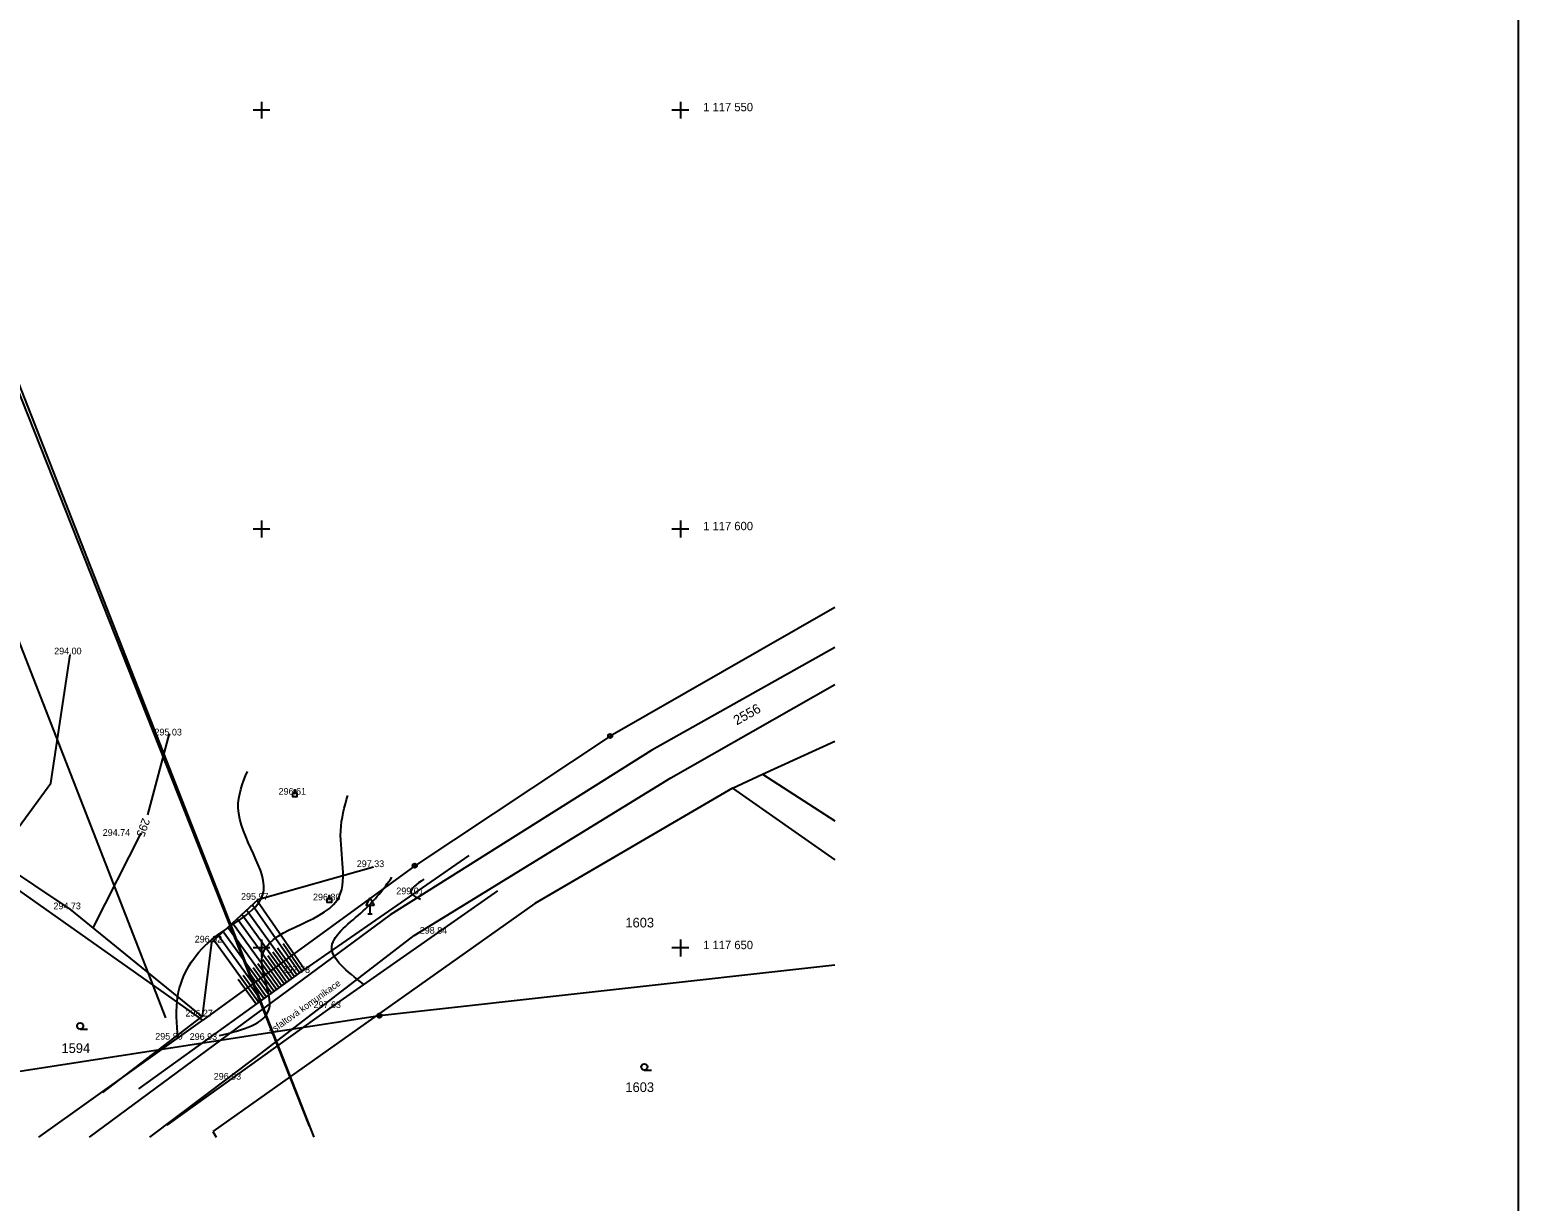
# Model space of a CAD drawing. Extents: x -504375 to -503125, y -1118000 to -1116474.
# Drawn here: x -503927.6 to -503750, y -1117680.2 to -1117540.4 of the extents above; entities that cross this region are included whole.
import ezdxf

# ---------------------------------------------------------------- set-up
doc = ezdxf.new("R2010")
doc.units = 0
for name, color, linetype in [('Druhy povrchů', 7, 'Continuous'), ('Elektro', 7, 'Continuous'), ('Komunikace', 7, 'Continuous'), ('Ploty', 7, 'Continuous'), ('Plynovod', 7, 'Continuous'), ('Podkladové mapy', 7, 'Continuous'), ('Síť dekadická', 7, 'Continuous'), ('Vrstva 34', 7, 'Continuous'), ('Vrstva 48', 7, 'Continuous'), ('Výškopis', 7, 'Continuous'), ('Výšky bodů plotr', 7, 'Continuous'), ('Značky ČSN', 7, 'Continuous')]:
    doc.layers.add(name, color=color, linetype=linetype)

msp = doc.modelspace()

# ---------------------------------------------------------------- linework, layer by layer
at = {"layer": 'Elektro'}
for points in [[(-503956.484, -1117542.839), (-503911.458, -1117658.334)], [(-503936.11, -1117565.73), (-503894.299, -1117671.279)]]:
    msp.add_lwpolyline(points, dxfattribs=at)
at = {"layer": 'Komunikace'}
for points in [[(-503875.235, -1117638.978), (-503895.47, -1117652.98), (-503914.65, -1117666.799)], [(-503911.247, -1117671.145), (-503891.78, -1117657.17), (-503871.792, -1117643.188)]]:
    msp.add_lwpolyline(points, dxfattribs=at)
at = {"layer": 'Ploty'}
msp.add_lwpolyline([(-503918.907, -1117667.255), (-503907.07, -1117658.18), (-503922.82, -1117645.38), (-503931.54, -1117639.57), (-503936.08, -1117638.16), (-503933.06, -1117633.02), (-504033.06, -1117569.97), (-504030.05, -1117581.29)], dxfattribs=at)
at = {"layer": 'Plynovod'}
for points in [[(-503896.264, -1117631.476), (-503895.76, -1117631.476), (-503895.76, -1117631.98), (-503896.264, -1117631.98)], [(-503892.154, -1117644.086), (-503891.65, -1117644.086), (-503891.65, -1117644.59), (-503892.154, -1117644.59)]]:
    msp.add_lwpolyline(points, close=True, dxfattribs=at)
for points in [[(-503895.949, -1117631.476), (-503895.949, -1117631.161), (-503896.075, -1117631.161), (-503896.075, -1117631.476)], [(-503891.839, -1117644.086), (-503891.839, -1117643.771), (-503891.965, -1117643.771), (-503891.965, -1117644.086)]]:
    msp.add_lwpolyline(points, dxfattribs=at)
at = {"layer": 'Podkladové mapy'}
for p, q in [((-503935.19, -1117566.81), (-503893.75, -1117672.579)), ((-503831.557, -1117609.37), (-503858.38, -1117624.71)), ((-503831.557, -1117614.147), (-503853.42, -1117626.38)), ((-503851.15, -1117629.69), (-503831.557, -1117618.557)), ((-503858.38, -1117624.71), (-503881.7, -1117640.18)), ((-503840.19, -1117629.27), (-503831.557, -1117625.306)), ((-503853.42, -1117626.38), (-503884.65, -1117646.03)), ((-503881.76, -1117648.52), (-503851.15, -1117629.69)), ((-503843.77, -1117630.91), (-503840.19, -1117629.27)), ((-503840.19, -1117629.27), (-503831.557, -1117634.845)), ((-503843.77, -1117630.91), (-503867.36, -1117644.69)), ((-503843.77, -1117630.91), (-503831.557, -1117639.488)), ((-503907.01, -1117658.6), (-503933.4, -1117639.97)), ((-503881.7, -1117640.18), (-503907.01, -1117658.6)), ((-503867.36, -1117644.69), (-503905.79, -1117671.91)), ((-503884.65, -1117646.03), (-503920.562, -1117672.584)), ((-503900.58, -1117663), (-503881.76, -1117648.52)), ((-503885.92, -1117658.08), (-503831.557, -1117652.028)), ((-503980.228, -1117672.595), (-503885.92, -1117658.08)), ((-503926.572, -1117672.585), (-503907.01, -1117658.6)), ((-503886.17, -1117658.03), (-503886.12, -1117657.93)), ((-503886.17, -1117658.13), (-503886.17, -1117658.03)), ((-503886.12, -1117658.23), (-503886.17, -1117658.13)), ((-503886.12, -1117657.93), (-503886.07, -1117657.88)), ((-503886.07, -1117658.28), (-503886.12, -1117658.23)), ((-503886.07, -1117657.88), (-503885.97, -1117657.83)), ((-503886.07, -1117657.98), (-503886.07, -1117658.18)), ((-503886.07, -1117658.18), (-503885.97, -1117658.23)), ((-503885.97, -1117658.33), (-503886.07, -1117658.28)), ((-503885.97, -1117657.83), (-503885.87, -1117657.83)), ((-503885.97, -1117658.23), (-503885.97, -1117657.93)), ((-503885.97, -1117657.93), (-503885.87, -1117657.93)), ((-503885.87, -1117658.33), (-503885.97, -1117658.33)), ((-503885.87, -1117657.83), (-503885.77, -1117657.88)), ((-503885.87, -1117657.93), (-503885.87, -1117658.23)), ((-503885.87, -1117658.23), (-503885.77, -1117658.18)), ((-503885.77, -1117658.28), (-503885.87, -1117658.33)), ((-503885.77, -1117657.88), (-503885.72, -1117657.93)), ((-503885.77, -1117658.18), (-503885.77, -1117657.98)), ((-503885.72, -1117658.23), (-503885.77, -1117658.28)), ((-503885.72, -1117657.93), (-503885.67, -1117658.03)), ((-503885.67, -1117658.13), (-503885.72, -1117658.23)), ((-503885.67, -1117658.03), (-503885.67, -1117658.13)), ((-503921.63, -1117659.69), (-503920.755, -1117659.69)), ((-503913.329, -1117672.583), (-503900.58, -1117663)), ((-503854.31, -1117664.58), (-503853.435, -1117664.58)), ((-503905.79, -1117671.91), (-503905.412, -1117672.582))]:
    msp.add_line(p, q, dxfattribs=at)
for centre, radius in [((-503858.38, -1117624.71), 0.25), ((-503858.38, -1117624.71), 0.005), ((-503881.7, -1117640.18), 0.25), ((-503881.7, -1117640.18), 0.005), ((-503921.63, -1117659.315), 0.375), ((-503854.31, -1117664.205), 0.375)]:
    msp.add_circle(centre, radius, dxfattribs=at)
at = {"layer": 'Síť dekadická'}
msp.add_lwpolyline([(-503750, -1117500), (-503750, -1118000), (-504375, -1118000), (-504375, -1117500)], close=True, dxfattribs=at)
at = {"layer": 'Vrstva 34'}
for p, q in [((-503899, -1117550), (-503901, -1117550)), ((-503900, -1117549), (-503900, -1117551)), ((-503849, -1117550), (-503851, -1117550)), ((-503850, -1117549), (-503850, -1117551)), ((-503899, -1117600), (-503901, -1117600)), ((-503900, -1117599), (-503900, -1117601)), ((-503849, -1117600), (-503851, -1117600)), ((-503850, -1117599), (-503850, -1117601)), ((-503899, -1117650), (-503901, -1117650)), ((-503900, -1117649), (-503900, -1117651)), ((-503849, -1117650), (-503851, -1117650)), ((-503850, -1117649), (-503850, -1117651))]:
    msp.add_line(p, q, dxfattribs=at)
at = {"layer": 'Vrstva 48'}
for p, q in [((-503913.569, -1117634.114), (-503910.98, -1117624.419)), ((-503920.051, -1117647.532), (-503914.365, -1117636.297))]:
    msp.add_line(p, q, dxfattribs=at)
msp.add_lwpolyline([(-503931.66, -1117639.187), (-503925.125, -1117630.342), (-503922.834, -1117614.998)], dxfattribs=at)
for points in [[(-503909.973, -1117660.783), (-503909.973, -1117655.708), (-503905.948, -1117649.023), (-503899.829, -1117643.626), (-503902.768, -1117633.276), (-503901.666, -1117628.921)], [(-503904.982, -1117660.461), (-503899.065, -1117657.246), (-503899.91, -1117651.037), (-503890.974, -1117644.311), (-503890.531, -1117636.015), (-503889.685, -1117631.786)], [(-503887.817, -1117654.32), (-503891.589, -1117649.81), (-503887.848, -1117645.577), (-503884.414, -1117641.558)], [(-503880.621, -1117641.805), (-503882.141, -1117643.441), (-503880.994, -1117644.187)]]:
    msp.add_spline(points, degree=3, dxfattribs=at)
at = {"layer": 'Výškopis'}
for p, q in [((-503895.468, -1117652.979), (-503901.088, -1117644.857)), ((-503894.852, -1117652.552), (-503900.531, -1117644.344)), ((-503897.294, -1117654.294), (-503902.894, -1117646.522)), ((-503896.685, -1117653.856), (-503902.338, -1117646.01)), ((-503896.077, -1117653.417), (-503901.783, -1117645.498)), ((-503899.119, -1117655.609), (-503904.559, -1117648.058)), ((-503898.511, -1117655.171), (-503904.004, -1117647.546)), ((-503897.902, -1117654.732), (-503903.449, -1117647.034)), ((-503900.336, -1117656.486), (-503905.67, -1117649.083)), ((-503899.728, -1117656.048), (-503905.115, -1117648.571)), ((-503895.773, -1117653.198), (-503898.066, -1117650.015)), ((-503895.16, -1117652.765), (-503897.42, -1117649.499)), ((-503898.207, -1117654.952), (-503900.415, -1117651.887)), ((-503897.598, -1117654.513), (-503899.827, -1117651.419)), ((-503896.99, -1117654.075), (-503899.24, -1117650.951)), ((-503896.381, -1117653.636), (-503898.653, -1117650.483)), ((-503900.032, -1117656.267), (-503902.176, -1117653.291)), ((-503899.424, -1117655.829), (-503901.589, -1117652.823)), ((-503898.815, -1117655.39), (-503901.002, -1117652.355)), ((-503900.641, -1117656.705), (-503902.764, -1117653.759))]:
    msp.add_line(p, q, dxfattribs=at)
for points in [[(-503886.62, -1117640.35), (-503900.43, -1117644.25)], [(-503900.43, -1117644.25), (-503905.96, -1117649.35)], [(-503905.96, -1117649.35), (-503907.07, -1117658.18)]]:
    msp.add_lwpolyline(points, dxfattribs=at)
at = {"layer": 'Značky ČSN'}
for p, q in [((-503887.05, -1117644.03), (-503887.55, -1117644.93)), ((-503887.05, -1117644.03), (-503886.55, -1117644.93)), ((-503886.55, -1117644.93), (-503887.55, -1117644.93)), ((-503887.3, -1117645.93), (-503886.8, -1117645.93)), ((-503887.05, -1117644.93), (-503887.05, -1117645.93))]:
    msp.add_line(p, q, dxfattribs=at)

# ---------------------------------------------------------------- texts
at = {"layer": 'Druhy povrchů'}
msp.add_text('asfaltová komunikace', height=0.8, rotation=35.67397, dxfattribs=at).set_placement((-503898.813, -1117660.373))
at = {"layer": 'Podkladové mapy'}
msp.add_text('2556', height=1.15, rotation=29.07081, dxfattribs=at).set_placement((-503843.27, -1117623.446))
for s, p in [('1603', (-503856.56, -1117647.549)), ('1594', (-503923.86, -1117662.53)), ('1603', (-503856.56, -1117667.19))]:
    msp.add_text(s, height=1.15, dxfattribs=at).set_placement(p)
at = {"layer": 'Vrstva 34'}
for s, p in [('1 117 550', (-503847.277, -1117550.143)), ('1 117 600', (-503847.277, -1117600.143)), ('1 117 650', (-503847.277, -1117650.143))]:
    msp.add_text(s, height=1, dxfattribs=at).set_placement(p)
at = {"layer": 'Vrstva 48'}
msp.add_text('295', height=1, rotation=249.99011, dxfattribs=at).set_placement((-503914.192, -1117634.42))
at = {"layer": 'Výšky bodů plotr'}
for s, p in [('294.00 ', (-503924.73, -1117614.96)), ('295.03 ', (-503912.76, -1117624.64)), ('296.61 ', (-503897.95, -1117631.71)), ('294.74 ', (-503918.94, -1117636.62)), ('297.33 ', (-503888.62, -1117640.35)), ('299.01 ', (-503883.9, -1117643.59)), ('294.73 ', (-503924.82, -1117645.38)), ('295.97 ', (-503902.43, -1117644.25)), ('296.80 ', (-503893.84, -1117644.32)), ('298.84 ', (-503881.1, -1117648.3)), ('296.02 ', (-503907.96, -1117649.35)), ('297.78 ', (-503897.47, -1117652.98)), ('297.63 ', (-503893.78, -1117657.17)), ('296.27 ', (-503909.07, -1117658.18)), ('295.80 ', (-503912.67, -1117660.94)), ('296.93 ', (-503908.56, -1117660.97)), ('296.93 ', (-503905.69, -1117665.72))]:
    msp.add_text(s, height=0.8, dxfattribs=at).set_placement(p)

doc.saveas('drawing.dxf')
